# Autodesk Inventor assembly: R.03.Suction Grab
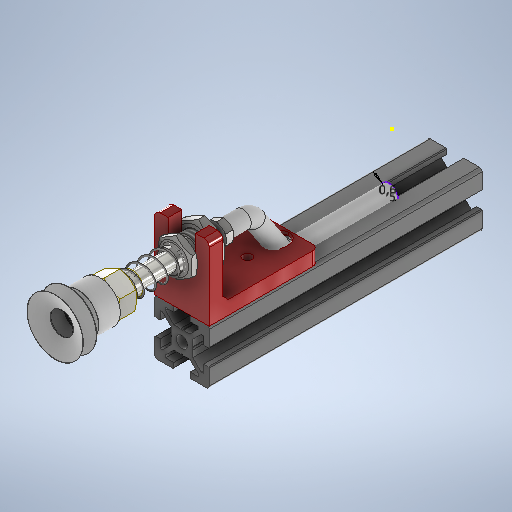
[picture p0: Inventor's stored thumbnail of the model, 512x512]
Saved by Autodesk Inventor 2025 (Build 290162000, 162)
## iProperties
Created: 2021-02
Part Number: R.03.Suction Grab
Document SubType Name: Assembly
Designer: Михальчик
Author: Михальчик
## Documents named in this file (11)
- C:\Users\Ryzen5700u\Desktop\ventosa\R.03.Suction Grab.iam
- C:\Users\Ryzen5700u\Desktop\ventosa\R.03.01.Cup.ipt
- C:\Users\Ryzen5700u\Desktop\ventosa\R.03.02.Tube.ipt
- C:\Users\Ryzen5700u\Desktop\ventosa\Compress Spring11.ipt
- C:\Users\Ryzen5700u\Desktop\ventosa\R.03.04.Fitting.ipt
- C:\Users\Ryzen5700u\Desktop\ventosa\DIN 3771 - 5 x 1,8 - N - NBR 70(2).ipt
- C:\Users\Ryzen5700u\Desktop\ventosa\R.03.05.Interface.ipt
- C:\Users\Ryzen5700u\Desktop\ventosa\R.03.06.Nut.ipt
- C:\Users\Ryzen5700u\Desktop\ventosa\blocco_ventosa_profilato.ipt
- C:\Users\Ryzen5700u\Desktop\ventosa\tslot-20x20-3.ipt
- C:\Users\Ryzen5700u\Desktop\ventosa\tubo_silicone.ipt
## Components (10 placed, 10 different names)
1. R.03.01.Cup:1 — Mate:1, Mate:2
2. R.03.02.Tube:1 — Mate:1, Mate:2, Mate:3, Flush:1, Mate:4, Mate:6, Rigido:1
3. R.03.03.Spring:1 — Mate:3, Flush:1, Mate:7
4. R.03.04.Fitting:1 — Mate:4, Rigido:1, Allineato:4
5. DIN 3771 - 5 x 1,8 - N - NBR 70(2):1 — Rotazionale:1
6. R.03.05.Interface:1 — Mate:6, Mate:7, Mate:8, Rotazionale:1, Rigido:2
7. R.03.06.Nut:1 — Mate:8, Coincidente:9
8. blocco_ventosa_profilato:1 — Rigido:2, Coincidente:9, Angolo:1, Coincidente:10, Allineato:2, Allineato:3
9. tslot-20x20-3:1 — Coincidente:10, Allineato:2, Allineato:3
10. tubo_silicone:1 — Allineato:4
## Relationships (17: Mate 9, Flush 4, WeldJoint 2, RevoluteJoint 1, Angle 1)
- Mate:1: R.03.01.Cup:1 ↔ R.03.02.Tube:1
- Mate:2: R.03.01.Cup:1 ↔ R.03.02.Tube:1
- Mate:3: R.03.02.Tube:1 ↔ R.03.03.Spring:1
- Flush:1: R.03.02.Tube:1 ↔ R.03.03.Spring:1
- Mate:4: R.03.02.Tube:1 ↔ R.03.04.Fitting:1
- Mate:6: R.03.02.Tube:1 ↔ R.03.05.Interface:1
- Mate:7: R.03.03.Spring:1 ↔ R.03.05.Interface:1
- Mate:8: R.03.05.Interface:1 ↔ R.03.06.Nut:1
- Rotazionale:1 [RevoluteJoint]: DIN 3771 - 5 x 1,8 - N - NBR 70(2):1 ↔ R.03.05.Interface:1
- Rigido:1 [WeldJoint]: R.03.02.Tube:1 ↔ R.03.04.Fitting:1
- Rigido:2 [WeldJoint]: R.03.05.Interface:1 ↔ blocco_ventosa_profilato:1
- Coincidente:9 [Mate]: R.03.06.Nut:1 ↔ blocco_ventosa_profilato:1
- Angolo:1 [Angle]: blocco_ventosa_profilato:1
- Coincidente:10 [Mate]: blocco_ventosa_profilato:1 ↔ tslot-20x20-3:1
- Allineato:2 [Flush]: blocco_ventosa_profilato:1 ↔ tslot-20x20-3:1
- Allineato:3 [Flush]: blocco_ventosa_profilato:1 ↔ tslot-20x20-3:1
- Allineato:4 [Flush]: R.03.04.Fitting:1 ↔ tubo_silicone:1
